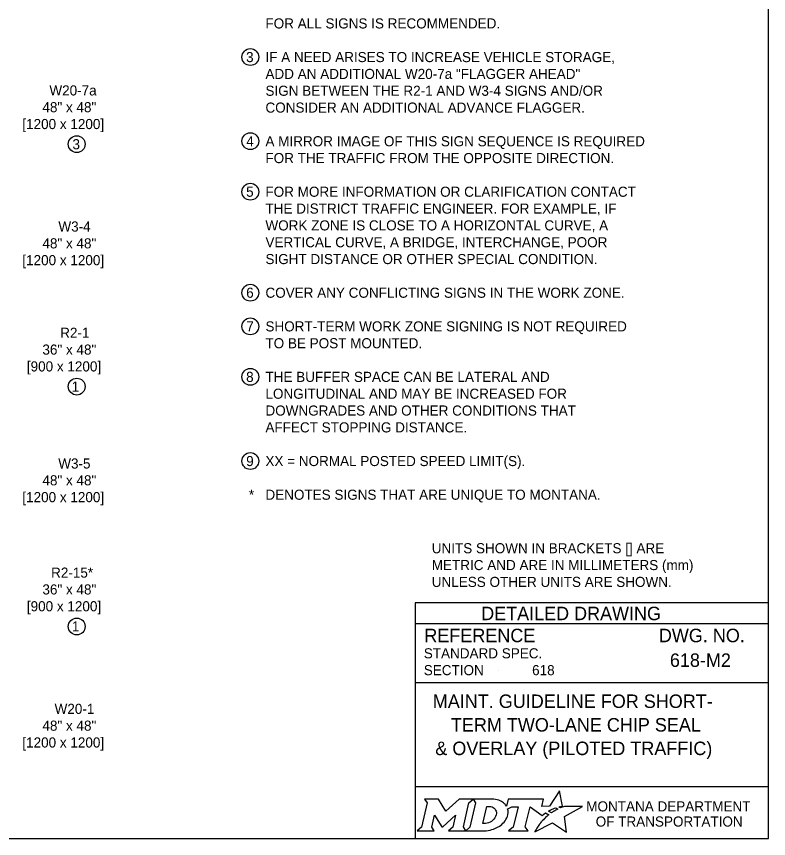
# Model space of a CAD drawing. Extents: x 49991.4 to 50021, y 49987.6 to 50011.4.
# Drawn here: x 50004.143 to 50008.615, y 50000.062 to 50004.947 of the extents above; entities that cross this region are included whole.
import ezdxf

# ---------------------------------------------------------------- set-up
doc = ezdxf.new("R2010")
doc.units = 0
doc.layers.add('Level 1', color=7, linetype='Continuous')
doc.layers.add('Level 2', color=7, linetype='Continuous')

msp = doc.modelspace()

# ---------------------------------------------------------------- linework, layer by layer
at = {"layer": 'Level 1'}
msp.add_lwpolyline([(50008.6146, 50011.2628), (50000.3356, 50011.2628), (50000.3356, 50000.0624), (50008.6146, 50000.0624)], close=True, dxfattribs=at)
at = {"layer": 'Level 2'}
for p, q in [((50004.4984, 50002.1908), (50004.4984, 50002.1908)), ((50008.6146, 50001.4624), (50006.5146, 50001.4624)), ((50006.5146, 50001.4624), (50006.5146, 50000.0624)), ((50008.6146, 50001.3374), (50006.5146, 50001.3374)), ((50008.2507, 50001.1223), (50008.2507, 50001.1223)), ((50007.0089, 50001.0629), (50007.0089, 50001.0629)), ((50008.6146, 50000.9874), (50006.5146, 50000.9874)), ((50007.5646, 50000.7383), (50007.5646, 50000.7383)), ((50008.6146, 50000.3693), (50006.5146, 50000.3693))]:
    msp.add_line(p, q, dxfattribs=at)
for points in [[(50007.3771, 50000.2447), (50007.3668, 50000.2503), (50007.3784, 50000.2531), (50007.39, 50000.2551), (50007.3726, 50000.3452), (50007.3131, 50000.2539), (50007.2658, 50000.2532), (50007.2761, 50000.2973), (50007.0669, 50000.2974), (50007.0568, 50000.2549), (50007.051, 50000.2632)], [(50006.5701, 50000.2974), (50006.5842, 50000.274), (50006.5507, 50000.1307), (50006.525, 50000.1082), (50006.6266, 50000.1082), (50006.6131, 50000.131), (50006.6293, 50000.2011), (50006.673, 50000.1321), (50006.6783, 50000.1321), (50006.7534, 50000.2016), (50006.737, 50000.1305), (50006.7123, 50000.1085), (50006.8139, 50000.1085), (50006.8001, 50000.1318), (50006.8333, 50000.2742)], [(50006.8333, 50000.2742), (50006.8586, 50000.2974), (50006.7762, 50000.2974), (50006.6966, 50000.2244), (50006.6521, 50000.2971), (50006.5701, 50000.2974)], [(50006.9722, 50000.2974), (50006.8586, 50000.2974), (50006.8733, 50000.2745), (50006.8394, 50000.1307), (50006.8139, 50000.1085), (50006.9245, 50000.1085)], [(50006.9962, 50000.2107), (50006.995, 50000.2026), (50006.9918, 50000.1933), (50006.9876, 50000.1851), (50006.982, 50000.1776), (50006.9755, 50000.1707), (50006.9676, 50000.1644), (50006.9593, 50000.1597), (50006.9502, 50000.1558), (50006.9411, 50000.1535), (50006.9319, 50000.1526), (50006.916, 50000.1526), (50006.9396, 50000.2526), (50006.9556, 50000.2526), (50006.9632, 50000.252), (50006.9708, 50000.2501), (50006.9774, 50000.2471), (50006.9835, 50000.2429), (50006.9883, 50000.2379), (50006.992, 50000.2319), (50006.9947, 50000.2257), (50006.9963, 50000.2183), (50006.9963, 50000.2153), (50006.9962, 50000.2107)], [(50007.0636, 50000.2383), (50007.0882, 50000.2514), (50007.1251, 50000.2514), (50007.0965, 50000.1309), (50007.069, 50000.1082), (50007.1852, 50000.1082), (50007.1682, 50000.1311), (50007.1964, 50000.2513), (50007.2677, 50000.1996), (50007.2888, 50000.2147), (50007.3085, 50000.2038)], [(50007.2527, 50000.1479), (50007.2374, 50000.1235), (50007.2327, 50000.116), (50007.2269, 50000.1074), (50007.2246, 50000.1031), (50007.3299, 50000.1562), (50007.4138, 50000.1011), (50007.4007, 50000.1938), (50007.5076, 50000.2522), (50007.4583, 50000.253), (50007.4282, 50000.2534), (50007.4074, 50000.2537), (50007.4006, 50000.2522), (50007.3957, 50000.251), (50007.3873, 50000.2487), (50007.3771, 50000.2447)], [(50007.3267, 50000.2171), (50007.3243, 50000.2154), (50007.306, 50000.225), (50007.3163, 50000.2307), (50007.3204, 50000.2329), (50007.329, 50000.2369), (50007.3347, 50000.2395), (50007.3426, 50000.2425), (50007.3499, 50000.2452), (50007.3617, 50000.2378), (50007.3577, 50000.2357), (50007.3531, 50000.2332), (50007.3489, 50000.231), (50007.3439, 50000.2281), (50007.342, 50000.227), (50007.3393, 50000.2254), (50007.3368, 50000.224), (50007.3345, 50000.2224), (50007.3319, 50000.2206), (50007.3292, 50000.2188), (50007.3267, 50000.2171)], [(50007.2666, 50000.164), (50007.2666, 50000.164)], [(50006.9702, 50000.1158), (50006.9786, 50000.1184), (50006.9916, 50000.1238), (50007.012, 50000.1348)]]:
    msp.add_lwpolyline(points, dxfattribs=at)
for centre in [(50005.5336, 50004.7053), (50005.5336, 50004.2053), (50004.5015, 50004.1876), (50005.5336, 50003.9053), (50005.5336, 50003.3053), (50005.5336, 50003.1053), (50005.5336, 50002.8053), (50004.5015, 50002.7476), (50005.5336, 50002.3053), (50004.5016, 50001.3226)]:
    msp.add_circle(centre, 0.05, dxfattribs=at)
for centre, radius, start, end in [((50006.9513, 50000.2363), 0.1183, 300.9103, 339.1383), ((50006.9953, 50000.219), 0.0709, 339.5329, 15.8582)]:
    msp.add_arc(centre, radius, start, end, dxfattribs=at)
for centre, major_axis, ratio, start_param, end_param in [((50006.9701, 50000.25), (0.0834, -0.0037), 0.568097, 0.61298, 1.570796), ((50007.0257, 50000.2573), (0.0361, -0.0295), 0.469099, 1.225588, 1.570796), ((50007.2974, 50000.1941), (-0.0112, -0.0097), 0.021651, 3.157348, 6.283185), ((50007.2597, 50000.1559), (-0.00694, -0.00806), 0.008222, 0, 3.137361), ((50007.2764, 50000.1742), (-0.0098, -0.0102), 0.016458, 3.141593, 6.279097), ((50006.9248, 50000.2568), (0, 0.1484), 0.987302, 3.139398, 3.456847)]:
    msp.add_ellipse(centre, major_axis=major_axis, ratio=ratio, start_param=start_param, end_param=end_param, dxfattribs=at)

# ---------------------------------------------------------------- texts
for s, height, p in [('FOR ALL SIGNS IS RECOMMENDED.', 0.06, (50005.6236, 50004.8753)), ('3', 0.06, (50005.5084, 50004.6753)), ('IF A NEED ARISES TO INCREASE VEHICLE STORAGE,', 0.06, (50005.6236, 50004.6753)), ('ADD AN ADDITIONAL W20-7a "FLAGGER AHEAD" ', 0.06, (50005.6236, 50004.5753)), ('W20-7a', 0.06, (50004.3392, 50004.4774)), ('SIGN BETWEEN THE R2-1 AND W3-4 SIGNS AND/OR', 0.06, (50005.6236, 50004.4753)), ('48" x 48"', 0.06, (50004.2977, 50004.3775)), ('CONSIDER AN ADDITIONAL ADVANCE FLAGGER.', 0.06, (50005.6236, 50004.3753)), ('[1200 x 1200]', 0.06, (50004.1783, 50004.2776)), ('3', 0.06, (50004.4763, 50004.1576)), ('4', 0.06, (50005.5096, 50004.1753)), ('A MIRROR IMAGE OF THIS SIGN SEQUENCE IS REQUIRED', 0.06, (50005.6236, 50004.1753)), ('FOR THE TRAFFIC FROM THE OPPOSITE DIRECTION.', 0.06, (50005.6236, 50004.0753)), ('5', 0.06, (50005.5087, 50003.8753)), ('FOR MORE INFORMATION OR CLARIFICATION CONTACT', 0.06, (50005.6236, 50003.8753)), ('THE DISTRICT TRAFFIC ENGINEER. FOR EXAMPLE, IF', 0.06, (50005.6236, 50003.7753)), ('W3-4', 0.06, (50004.3927, 50003.6686)), ('WORK ZONE IS CLOSE TO A HORIZONTAL CURVE, A', 0.06, (50005.6236, 50003.6753)), ('48" x 48"', 0.06, (50004.2977, 50003.5687)), ('VERTICAL CURVE, A BRIDGE, INTERCHANGE, POOR', 0.06, (50005.6236, 50003.5753)), ('[1200 x 1200]', 0.06, (50004.1783, 50003.4688)), ('SIGHT DISTANCE OR OTHER SPECIAL CONDITION. ', 0.06, (50005.6236, 50003.4753)), ('6', 0.06, (50005.5091, 50003.2753)), ('COVER ANY CONFLICTING SIGNS IN THE WORK ZONE.', 0.06, (50005.6236, 50003.2753)), ('7', 0.06, (50005.5098, 50003.0753)), ('SHORT-TERM WORK ZONE SIGNING IS NOT REQUIRED', 0.06, (50005.6236, 50003.0753)), ('R2-1', 0.06, (50004.4033, 50003.0374)), ('TO BE POST MOUNTED. ', 0.06, (50005.6236, 50002.9753)), ('36" x 48"', 0.06, (50004.2977, 50002.9375)), ('[900 x 1200]', 0.06, (50004.2052, 50002.8376)), ('8', 0.06, (50005.5086, 50002.7753)), ('THE BUFFER SPACE CAN BE LATERAL AND', 0.06, (50005.6236, 50002.7753)), ('1', 0.06, (50004.4717, 50002.7176)), ('LONGITUDINAL AND MAY BE INCREASED FOR', 0.06, (50005.6236, 50002.6753)), ('DOWNGRADES AND OTHER CONDITIONS THAT', 0.06, (50005.6236, 50002.5753)), ('AFFECT STOPPING DISTANCE.', 0.06, (50005.6236, 50002.4753)), ('W3-5', 0.06, (50004.3918, 50002.2607)), ('9', 0.06, (50005.5091, 50002.2753)), ('XX = NORMAL POSTED SPEED LIMIT(S).', 0.06, (50005.6236, 50002.2753)), ('48" x 48"', 0.06, (50004.2977, 50002.1608)), ('[1200 x 1200]', 0.06, (50004.1783, 50002.0609)), ('*', 0.06, (50005.525, 50002.0753)), ('DENOTES SIGNS THAT ARE UNIQUE TO MONTANA.', 0.06, (50005.6236, 50002.0753)), ('UNITS SHOWN IN BRACKETS [] ARE ', 0.06, (50006.6123, 50001.7573)), ('METRIC AND ARE IN MILLIMETERS (mm) ', 0.06, (50006.6123, 50001.6573)), ('R2-15*', 0.06, (50004.3493, 50001.6124)), ('UNLESS OTHER UNITS ARE SHOWN.', 0.06, (50006.6123, 50001.5573)), ('36" x 48"', 0.06, (50004.2977, 50001.5125)), ('[900 x 1200]', 0.06, (50004.2052, 50001.4126)), ('DETAILED DRAWING', 0.0799, (50006.9063, 50001.3599)), ('1', 0.06, (50004.4728, 50001.2926)), ('REFERENCE', 0.08, (50006.5682, 50001.229)), ('DWG. NO.', 0.08, (50007.9624, 50001.229)), ('STANDARD SPEC.', 0.06, (50006.5649, 50001.133)), ('618-M2', 0.08, (50008.0281, 50001.0823)), ('SECTION', 0.06, (50006.5649, 50001.033)), ('618', 0.06, (50007.2089, 50001.0329)), ('MAINT. GUIDELINE FOR SHORT-', 0.08, (50006.6185, 50000.8383)), ('W20-1', 0.06, (50004.37, 50000.803)), ('TERM TWO-LANE CHIP SEAL', 0.08, (50006.7261, 50000.6983)), ('48" x 48"', 0.06, (50004.2977, 50000.7031)), ('[1200 x 1200]', 0.06, (50004.1783, 50000.6032)), ('& OVERLAY (PILOTED TRAFFIC)', 0.08, (50006.6335, 50000.5583)), ('MONTANA DEPARTMENT', 0.06, (50007.5308, 50000.2236)), ('OF TRANSPORTATION', 0.06, (50007.587, 50000.1336))]:
    msp.add_text(s, height=height, dxfattribs=at).set_placement(p)

doc.saveas('drawing.dxf')
